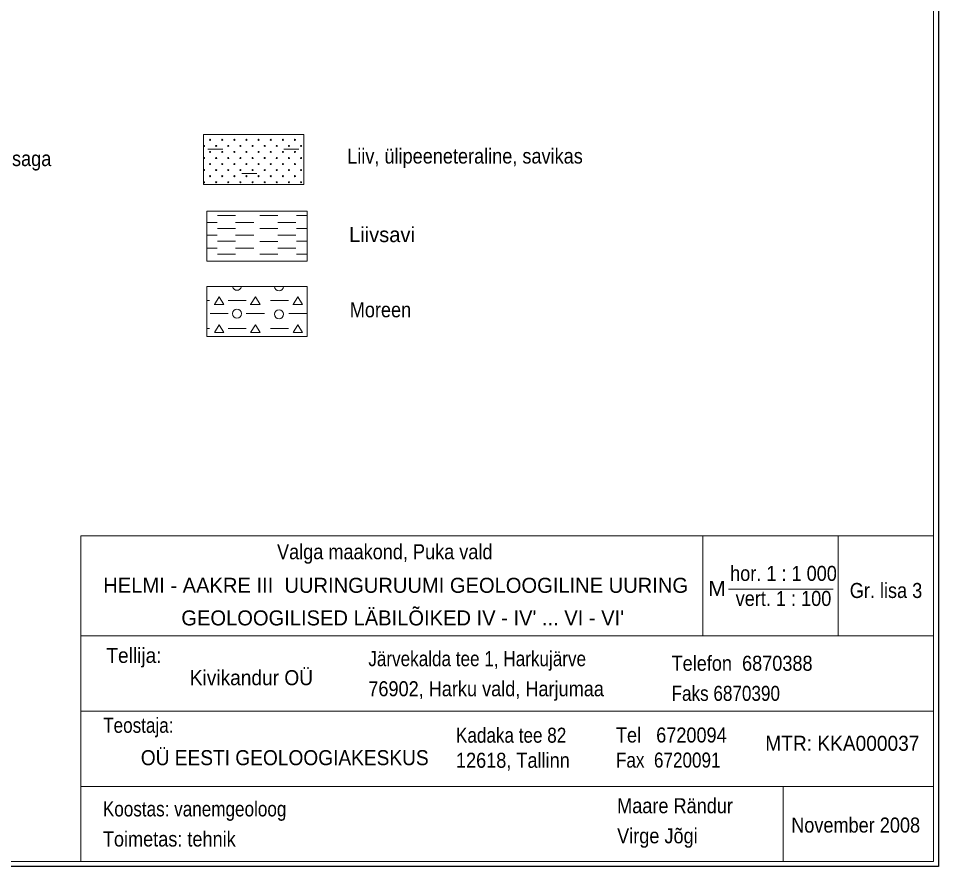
# Model space of a CAD drawing. Extents: x 640121 to 640955, y 6441885 to 6442246.
# Drawn here: x 640771.8 to 640955.2, y 6441889.4 to 6442058.6 of the extents above; entities that cross this region are included whole.
import ezdxf
from ezdxf.enums import TextEntityAlignment as Align

# ---------------------------------------------------------------- set-up
doc = ezdxf.new("R2010")
doc.units = 0
doc.header["$LTSCALE"] = 1.2
doc.layers.add('50', color=7, linetype='Continuous', lineweight=13)

msp = doc.modelspace()

# ---------------------------------------------------------------- hatches: boundary and pattern name
at = {"layer": '50'}
for points in [[(640810.077, 6442034.446, 1), (640809.929, 6442034.297, 1)], [(640811.287, 6442033.237, 1), (640811.138, 6442033.088, 1)], [(640812.496, 6442034.446, 1), (640812.347, 6442034.297, 1)], [(640813.705, 6442033.237, 1), (640813.556, 6442033.088, 1)], [(640814.914, 6442034.446, 1), (640814.765, 6442034.297, 1)], [(640816.123, 6442033.237, 1), (640815.975, 6442033.088, 1)], [(640817.332, 6442034.446, 1), (640817.184, 6442034.297, 1)], [(640818.541, 6442033.237, 1), (640818.393, 6442033.088, 1)], [(640819.751, 6442034.446, 1), (640819.602, 6442034.297, 1)], [(640820.96, 6442033.237, 1), (640820.811, 6442033.088, 1)], [(640822.169, 6442034.446, 1), (640822.02, 6442034.297, 1)], [(640823.378, 6442033.237, 1), (640823.23, 6442033.088, 1)], [(640824.587, 6442034.446, 1), (640824.439, 6442034.297, 1)], [(640825.796, 6442033.237, 1), (640825.648, 6442033.088, 1)], [(640827.005, 6442034.446, 1), (640826.857, 6442034.297, 1)], [(640828.215, 6442033.237, 1), (640828.066, 6442033.088, 1)], [(640810.077, 6442032.028, 1), (640809.929, 6442031.879, 1)], [(640812.496, 6442032.028, 1), (640812.347, 6442031.879, 1)], [(640814.914, 6442032.028, 1), (640814.765, 6442031.879, 1)], [(640817.332, 6442032.028, 1), (640817.184, 6442031.879, 1)], [(640819.751, 6442032.028, 1), (640819.602, 6442031.879, 1)], [(640822.169, 6442032.028, 1), (640822.02, 6442031.879, 1)], [(640824.587, 6442032.028, 1), (640824.439, 6442031.879, 1)], [(640827.005, 6442032.028, 1), (640826.857, 6442031.879, 1)], [(640810.077, 6442029.609, 1), (640809.929, 6442029.461, 1)], [(640811.287, 6442030.818, 1), (640811.138, 6442030.67, 1)], [(640812.496, 6442029.609, 1), (640812.347, 6442029.461, 1)], [(640813.705, 6442030.818, 1), (640813.556, 6442030.67, 1)], [(640814.914, 6442029.609, 1), (640814.765, 6442029.461, 1)], [(640816.123, 6442030.818, 1), (640815.975, 6442030.67, 1)], [(640817.332, 6442029.609, 1), (640817.184, 6442029.461, 1)], [(640818.541, 6442030.818, 1), (640818.393, 6442030.67, 1)], [(640819.751, 6442029.609, 1), (640819.602, 6442029.461, 1)], [(640820.96, 6442030.818, 1), (640820.811, 6442030.67, 1)], [(640822.169, 6442029.609, 1), (640822.02, 6442029.461, 1)], [(640823.378, 6442030.818, 1), (640823.23, 6442030.67, 1)], [(640824.587, 6442029.609, 1), (640824.439, 6442029.461, 1)], [(640825.796, 6442030.818, 1), (640825.648, 6442030.67, 1)], [(640827.005, 6442029.609, 1), (640826.857, 6442029.461, 1)], [(640828.215, 6442030.818, 1), (640828.066, 6442030.67, 1)], [(640811.287, 6442028.4, 1), (640811.138, 6442028.252, 1)], [(640813.705, 6442028.4, 1), (640813.556, 6442028.252, 1)], [(640816.123, 6442028.4, 1), (640815.975, 6442028.252, 1)], [(640818.541, 6442028.4, 1), (640818.393, 6442028.252, 1)], [(640820.96, 6442028.4, 1), (640820.811, 6442028.252, 1)], [(640823.378, 6442028.4, 1), (640823.23, 6442028.252, 1)], [(640825.796, 6442028.4, 1), (640825.648, 6442028.252, 1)], [(640828.215, 6442028.4, 1), (640828.066, 6442028.252, 1)], [(640810.077, 6442027.191, 1), (640809.929, 6442027.043, 1)], [(640811.287, 6442025.982, 1), (640811.138, 6442025.833, 1)], [(640812.496, 6442027.191, 1), (640812.347, 6442027.043, 1)], [(640813.705, 6442025.982, 1), (640813.556, 6442025.833, 1)], [(640814.914, 6442027.191, 1), (640814.765, 6442027.043, 1)], [(640816.123, 6442025.982, 1), (640815.975, 6442025.833, 1)], [(640817.332, 6442027.191, 1), (640817.184, 6442027.043, 1)], [(640818.541, 6442025.982, 1), (640818.393, 6442025.833, 1)], [(640819.751, 6442027.191, 1), (640819.602, 6442027.043, 1)], [(640820.96, 6442025.982, 1), (640820.811, 6442025.833, 1)], [(640822.169, 6442027.191, 1), (640822.02, 6442027.043, 1)], [(640823.378, 6442025.982, 1), (640823.23, 6442025.833, 1)], [(640824.587, 6442027.191, 1), (640824.439, 6442027.043, 1)], [(640825.796, 6442025.982, 1), (640825.648, 6442025.833, 1)], [(640827.005, 6442027.191, 1), (640826.857, 6442027.043, 1)], [(640828.215, 6442025.982, 1), (640828.066, 6442025.833, 1)]]:
    msp.add_hatch(color=256, dxfattribs=at).paths.add_polyline_path(points)

# ---------------------------------------------------------------- linework, layer by layer
for p, q in [((640809.57, 6442032.51), (640812.57, 6442032.51)), ((640824.7, 6442032.51), (640827.7, 6442032.51)), ((640816.32, 6442027.66), (640819.32, 6442027.66)), ((640815.1, 6442019.27), (640811.5, 6442019.27)), ((640823.5, 6442019.26), (640819.9, 6442019.26)), ((640829.33, 6442019.27), (640827.21, 6442019.27)), ((640811.4, 6442017.9), (640809.33, 6442017.9)), ((640815.1, 6442016.7), (640811.5, 6442016.7)), ((640818.7, 6442017.9), (640815.1, 6442017.9)), ((640823.5, 6442016.69), (640819.9, 6442016.69)), ((640827.11, 6442017.9), (640823.51, 6442017.9)), ((640829.33, 6442016.7), (640827.21, 6442016.7)), ((640811.4, 6442015.33), (640809.33, 6442015.33)), ((640818.7, 6442015.33), (640815.1, 6442015.33)), ((640827.11, 6442015.33), (640823.51, 6442015.33)), ((640815.1, 6442014.13), (640811.5, 6442014.13)), ((640823.5, 6442014.12), (640819.9, 6442014.12)), ((640829.33, 6442014.13), (640827.21, 6442014.13)), ((640811.4, 6442012.76), (640809.33, 6442012.76)), ((640815.1, 6442011.56), (640811.5, 6442011.56)), ((640818.7, 6442012.76), (640815.1, 6442012.76)), ((640823.5, 6442011.55), (640819.9, 6442011.55)), ((640827.11, 6442012.76), (640823.51, 6442012.76)), ((640829.33, 6442011.56), (640827.21, 6442011.56)), ((640811.4, 6442010.19), (640809.33, 6442010.19)), ((640818.7, 6442010.19), (640815.1, 6442010.19)), ((640827.11, 6442010.19), (640823.51, 6442010.19)), ((640809.92, 6442002.31), (640809.38, 6442002.31)), ((640817.22, 6442002.31), (640813.62, 6442002.31)), ((640825.62, 6442002.31), (640822.02, 6442002.31)), ((640829.38, 6442002.31), (640829.31, 6442002.31)), ((640813.62, 6441999.75), (640810.02, 6441999.75)), ((640820.82, 6441999.75), (640817.22, 6441999.75)), ((640829.31, 6441999.75), (640825.71, 6441999.75)), ((640809.92, 6441996.76), (640809.38, 6441996.76)), ((640817.22, 6441996.75), (640813.62, 6441996.75)), ((640825.62, 6441996.76), (640822.02, 6441996.76)), ((640829.38, 6441996.75), (640829.31, 6441996.75)), ((640908.22, 6441935.4), (640908.22, 6441955.4)), ((640935.23, 6441935.4), (640935.23, 6441955.4)), ((640913.35, 6441944.73), (640934.23, 6441944.73)), ((640784.23, 6441935.4), (640954.23, 6441935.4)), ((640799.75, 6441932.17), (640799.73, 6441932.15)), ((640784.23, 6441920.4), (640954.23, 6441920.4)), ((640784.23, 6441905.4), (640954.23, 6441905.4)), ((640924.23, 6441890.4), (640924.23, 6441905.4))]:
    msp.add_line(p, q, dxfattribs=at)
at = {"layer": '50', "lineweight": 25}
msp.add_lwpolyline([(640121.33, 6442246.16), (640955.23, 6442246.16), (640955.23, 6441889.4), (640121.33, 6441889.4)], close=True, dxfattribs=at)
at = {"layer": '50'}
for points in [[(640122.33, 6442245.16), (640954.23, 6442245.16), (640954.23, 6441890.4), (640122.33, 6441890.4)], [(640808.71, 6442035.43), (640828.71, 6442035.43), (640828.71, 6442025.43), (640808.71, 6442025.43)], [(640809.33, 6442020.14), (640829.33, 6442020.14), (640829.33, 6442010.14), (640809.33, 6442010.14)], [(640809.38, 6442005.12), (640829.38, 6442005.12), (640829.38, 6441995.12), (640809.38, 6441995.12)], [(640954.23, 6441955.4), (640784.23, 6441955.4), (640784.23, 6441890.4), (640954.23, 6441890.4)]]:
    msp.add_lwpolyline(points, close=True, dxfattribs=at)
for points in [[(640810.86, 6442001.48), (640810.86, 6442001.5), (640811.81, 6442003.03), (640812.74, 6442001.49), (640810.94, 6442001.5)], [(640818.08, 6442001.48), (640818.08, 6442001.5), (640819.03, 6442003.03), (640819.96, 6442001.49), (640818.16, 6442001.5)], [(640826.55, 6442001.48), (640826.55, 6442001.5), (640827.5, 6442003.03), (640828.43, 6442001.49), (640826.63, 6442001.5)], [(640810.86, 6441995.93), (640810.86, 6441995.95), (640811.81, 6441997.48), (640812.74, 6441995.94), (640810.94, 6441995.95)], [(640818.08, 6441995.93), (640818.08, 6441995.95), (640819.03, 6441997.48), (640819.96, 6441995.94), (640818.16, 6441995.95)], [(640826.55, 6441995.93), (640826.55, 6441995.95), (640827.5, 6441997.48), (640828.43, 6441995.94), (640826.63, 6441995.95)]]:
    msp.add_lwpolyline(points, dxfattribs=at)
for centre, radius in [((640810.003, 6442034.372), 0.105), ((640811.212, 6442033.163), 0.105), ((640812.421, 6442034.372), 0.105), ((640813.631, 6442033.163), 0.105), ((640814.84, 6442034.372), 0.105), ((640816.049, 6442033.163), 0.105), ((640817.258, 6442034.372), 0.105), ((640818.467, 6442033.163), 0.105), ((640819.676, 6442034.372), 0.105), ((640820.885, 6442033.163), 0.105), ((640822.095, 6442034.372), 0.105), ((640823.304, 6442033.163), 0.105), ((640824.513, 6442034.372), 0.105), ((640825.722, 6442033.163), 0.105), ((640826.931, 6442034.372), 0.105), ((640828.14, 6442033.163), 0.105), ((640810.003, 6442031.953), 0.105), ((640812.421, 6442031.953), 0.105), ((640814.84, 6442031.953), 0.105), ((640817.258, 6442031.953), 0.105), ((640819.676, 6442031.953), 0.105), ((640822.095, 6442031.953), 0.105), ((640824.513, 6442031.953), 0.105), ((640826.931, 6442031.953), 0.105), ((640810.003, 6442029.535), 0.105), ((640811.212, 6442030.744), 0.105), ((640812.421, 6442029.535), 0.105), ((640813.631, 6442030.744), 0.105), ((640814.84, 6442029.535), 0.105), ((640816.049, 6442030.744), 0.105), ((640817.258, 6442029.535), 0.105), ((640818.467, 6442030.744), 0.105), ((640819.676, 6442029.535), 0.105), ((640820.885, 6442030.744), 0.105), ((640822.095, 6442029.535), 0.105), ((640823.304, 6442030.744), 0.105), ((640824.513, 6442029.535), 0.105), ((640825.722, 6442030.744), 0.105), ((640826.931, 6442029.535), 0.105), ((640828.14, 6442030.744), 0.105), ((640811.212, 6442028.326), 0.105), ((640813.631, 6442028.326), 0.105), ((640816.049, 6442028.326), 0.105), ((640818.467, 6442028.326), 0.105), ((640820.885, 6442028.326), 0.105), ((640823.304, 6442028.326), 0.105), ((640825.722, 6442028.326), 0.105), ((640828.14, 6442028.326), 0.105), ((640810.003, 6442027.117), 0.105), ((640811.212, 6442025.908), 0.105), ((640812.421, 6442027.117), 0.105), ((640813.631, 6442025.908), 0.105), ((640814.84, 6442027.117), 0.105), ((640816.049, 6442025.908), 0.105), ((640817.258, 6442027.117), 0.105), ((640818.467, 6442025.908), 0.105), ((640819.676, 6442027.117), 0.105), ((640820.885, 6442025.908), 0.105), ((640822.095, 6442027.117), 0.105), ((640823.304, 6442025.908), 0.105), ((640824.513, 6442027.117), 0.105), ((640825.722, 6442025.908), 0.105), ((640826.931, 6442027.117), 0.105), ((640828.14, 6442025.908), 0.105), ((640815.365, 6441999.702), 0.9), ((640823.747, 6441999.58), 0.9)]:
    msp.add_circle(centre, radius, dxfattribs=at)
for centre, radius, start, end in [((640808.794, 6442033.163), 0.105, 212.33453, 147.66547), ((640808.794, 6442030.744), 0.105, 212.33453, 147.66547), ((640808.794, 6442028.326), 0.105, 212.33453, 147.66547), ((640808.794, 6442025.908), 0.105, 212.33453, 147.66547), ((640815.365, 6442005.256), 0.9, 188.96929, 351.03071), ((640823.747, 6442005.134), 0.9, 181.15583, 358.84417)]:
    msp.add_arc(centre, radius, start, end, dxfattribs=at)

# ---------------------------------------------------------------- texts
for s, width, p in [('Liiv, keskmiseteraline, vähese kruusaga', 0.9, (640746.445, 6442029.13)), ('Liiv, ülipeeneteraline, savikas', 0.9, (640860.825, 6442029.64)), ('Moreen', 0.9, (640843.97, 6441998.97)), ('Valga maakond, Puka vald', 0.9, (640844.825, 6441950.71)), ('hor. 1 : 1 000', 0.9, (640924.31, 6441946.39)), ('M', 1.05, (640911.065, 6441943.4)), ('Gr. lisa 3', 0.9, (640944.745, 6441942.98)), ('vert. 1 : 100', 0.9, (640924.31, 6441941.39)), ('     Kivikandur OÜ', 0.95, (640815.595, 6441925.59)), ('November 2008', 0.9, (640938.695, 6441896.19))]:
    msp.add_text(s, height=3, dxfattribs=dict(at, width=width)).set_placement(p, align=Align.CENTER)
for s, p in [('Liivsavi', (640844.27, 6442013.97)), ('HELMI - AAKRE III  UURINGURUUMI GEOLOOGILINE UURING', (640847, 6441944.01)), ("GEOLOOGILISED LÄBILÕIKED IV - IV' ... VI - VI'", (640848.4, 6441937.51))]:
    msp.add_text(s, height=3, dxfattribs=at).set_placement(p, align=Align.CENTER)
for s, width, p in [('Tellija:', 0.95, (640789.32, 6441930.03)), ('Järvekalda tee 1, Harkujärve', 0.85, (640841.55, 6441929.38)), ('Telefon  6870388', 0.9, (640902, 6441928.46)), ('76902, Harku vald, Harjumaa', 0.9, (640841.55, 6441923.38)), ('Faks 6870390', 0.85, (640902, 6441922.46)), ('Teostaja:', 0.85, (640788.69, 6441916.09)), ('Kadaka tee 82', 0.85, (640859.02, 6441914.11)), ('Tel   6720094', 0.9, (640890.91, 6441914.15)), ('MTR: KKA000037', 0.95, (640920.69, 6441912.5)), ('OÜ EESTI GEOLOOGIAKESKUS', 0.95, (640796.19, 6441909.63)), ('12618, Tallinn', 0.9, (640859.02, 6441909.11)), ('Fax  6720091', 0.85, (640890.91, 6441909.15)), ('Maare Rändur', 0.9, (640891.15, 6441900.05)), ('Koostas: vanemgeoloog', 0.85, (640788.63, 6441899.41)), ('Toimetas: tehnik', 0.9, (640788.63, 6441893.41)), ('Virge Jõgi', 0.9, (640891.15, 6441894.05))]:
    msp.add_text(s, height=3, dxfattribs=dict(at, width=width)).set_placement(p)

doc.saveas('drawing.dxf')
